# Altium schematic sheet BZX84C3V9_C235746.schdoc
size 127 x 101 mm
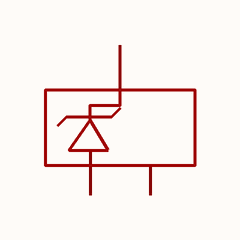
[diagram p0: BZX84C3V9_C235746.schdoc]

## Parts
D?  bzx84c3v9  [SOT-23-3_L3.0-W1.7-P0.95-LS2.9-BR]  (value not drawn)

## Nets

Not connected (* = marked no-connect by the designer): D? 1(A) 2 3(K)

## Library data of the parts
D? = bzx84c3v9: 二极管配置:1个独立式;稳压值(标称值):3.9V;稳压值(范围):3.7V~4.1V;耗散功率(Pd):300mW;; Manufacturer: CJ(江苏长电/长晶); Symbol: BZX84C3V9_C235746; AddInBom: yes; ModelId: 89cb27a44ab2466697082bb9fd73a7d0; ModelName: SOT-23-3L_L2.9-W1.6-H1.1-LS2.8-P0.95; ModelTransform: 114.173,110.236,0,90,0,0,0,0,0; Diode Configuration: 1个独立式; Zener Voltage(Nom): 3.9V; Reverse Leakage Current (Ir): 3uA@1V; Pd - Power Dissipation: 300mW; Impedance(Zzt): 90Ω; Impedance(Zzk): 600Ω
